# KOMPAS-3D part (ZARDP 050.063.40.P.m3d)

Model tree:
1. Плоскость XY
2. Плоскость ZX
3. Плоскость ZY
4. Ось X
5. Ось Y
6. Ось Z
7. Начало координат
8. Смещенная плоскость:1
     Расстояние = 132
9. Ось конической поверхности:2
10. Булева операция:1
11. Булева операция:2
12. Булева операция:3
13. Булева операция:4
14. Булева операция:5
15. Булева операция:6
16. Булева операция:7
17. Булева операция:8
18. Булева операция:9
